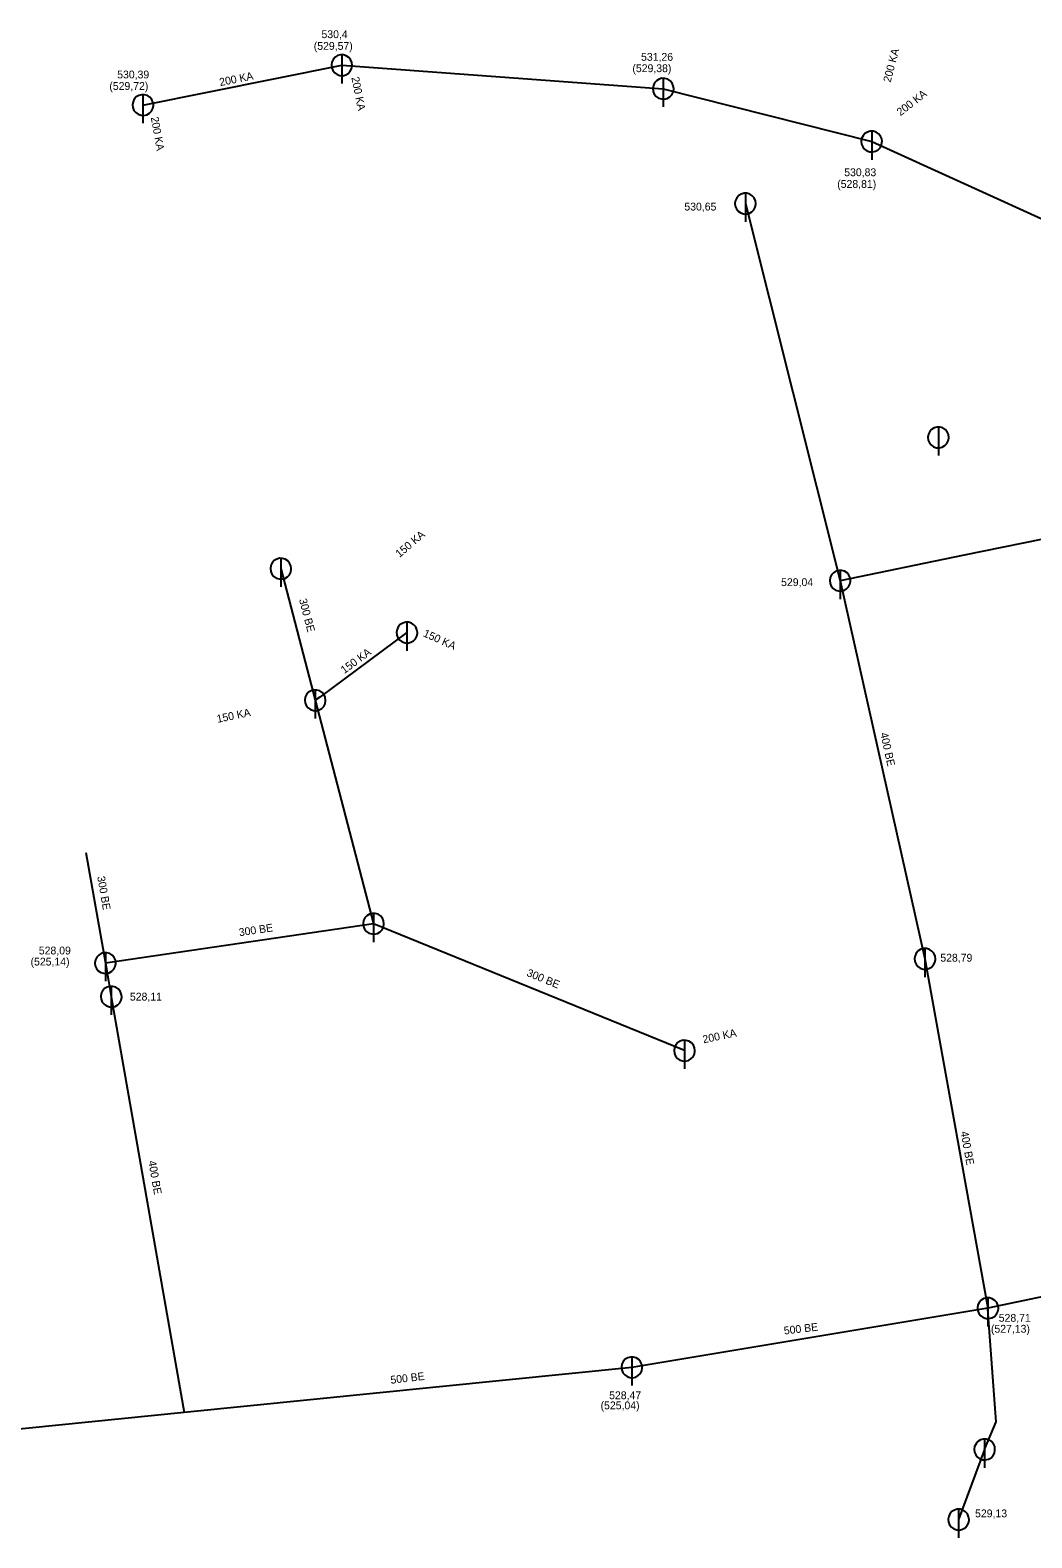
# Model space of a CAD drawing. Extents: x -476058 to -471893, y -1155786 to -1152000.
# Drawn here: x -473502.4 to -473406.3, y -1153921.9 to -1153777.4 of the extents above; entities that cross this region are included whole.
import ezdxf

# ---------------------------------------------------------------- set-up
doc = ezdxf.new("R2010")
doc.units = 0
for name, color, linetype in [('Vrstva 10', 7, 'Continuous'), ('Vrstva 18', 7, 'Continuous'), ('Vrstva 19', 7, 'Continuous'), ('Vrstva 3', 7, 'Continuous'), ('Vrstva 35', 7, 'Continuous'), ('Vrstva 4', 7, 'Continuous'), ('Vrstva 45', 7, 'Continuous'), ('Vrstva 46', 7, 'Continuous'), ('Vrstva 50', 7, 'Continuous'), ('Vrstva 51', 7, 'Continuous')]:
    doc.layers.add(name, color=color, linetype=linetype)

msp = doc.modelspace()

# ---------------------------------------------------------------- linework, layer by layer
at = {"layer": 'Vrstva 10'}
for p, q in [((-473472.48, -1153779.81), (-473472.48, -1153782.56)), ((-473441.67, -1153782.06), (-473441.67, -1153784.8)), ((-473491.54, -1153783.62), (-473491.54, -1153786.37)), ((-473421.7, -1153787.12), (-473421.7, -1153789.87)), ((-473433.8, -1153793.07), (-473433.8, -1153795.82)), ((-473415.31, -1153815.47), (-473415.31, -1153818.22)), ((-473478.32, -1153828.05), (-473478.32, -1153830.8)), ((-473424.72, -1153829.21), (-473424.72, -1153831.96)), ((-473466.24, -1153834.18), (-473466.24, -1153836.93)), ((-473475.03, -1153840.66), (-473475.03, -1153843.41)), ((-473469.44, -1153862.08), (-473469.44, -1153864.83)), ((-473495.14, -1153865.85), (-473495.14, -1153868.59)), ((-473416.59, -1153865.45), (-473416.59, -1153868.2)), ((-473494.58, -1153869.07), (-473494.58, -1153871.82)), ((-473439.64, -1153874.24), (-473439.64, -1153876.99)), ((-473410.56, -1153898.92), (-473410.56, -1153901.67)), ((-473444.68, -1153904.59), (-473444.68, -1153907.34)), ((-473410.88, -1153912.47), (-473410.88, -1153915.21)), ((-473413.37, -1153919.18), (-473413.37, -1153921.93))]:
    msp.add_line(p, q, dxfattribs=at)
for points in [[(-473471.48, -1153780.81), (-473471.52, -1153780.53), (-473471.64, -1153780.27), (-473471.82, -1153780.06), (-473472.05, -1153779.91), (-473472.33, -1153779.82), (-473472.61, -1153779.82), (-473472.88, -1153779.89), (-473473.12, -1153780.04), (-473473.31, -1153780.25), (-473473.43, -1153780.5), (-473473.48, -1153780.78), (-473473.45, -1153781.06), (-473473.34, -1153781.32), (-473473.16, -1153781.54), (-473472.93, -1153781.7), (-473472.66, -1153781.79), (-473472.38, -1153781.81), (-473472.11, -1153781.74), (-473471.86, -1153781.6), (-473471.67, -1153781.39), (-473471.54, -1153781.14), (-473471.48, -1153780.87), (-473471.48, -1153780.81)], [(-473440.67, -1153783.06), (-473440.71, -1153782.78), (-473440.83, -1153782.52), (-473441.01, -1153782.31), (-473441.25, -1153782.15), (-473441.52, -1153782.07), (-473441.8, -1153782.06), (-473442.07, -1153782.14), (-473442.31, -1153782.29), (-473442.5, -1153782.5), (-473442.62, -1153782.75), (-473442.67, -1153783.03), (-473442.64, -1153783.31), (-473442.53, -1153783.57), (-473442.35, -1153783.79), (-473442.12, -1153783.95), (-473441.85, -1153784.04), (-473441.57, -1153784.05), (-473441.3, -1153783.99), (-473441.05, -1153783.84), (-473440.86, -1153783.64), (-473440.73, -1153783.39), (-473440.67, -1153783.11), (-473440.67, -1153783.06)], [(-473490.54, -1153784.62), (-473490.58, -1153784.34), (-473490.7, -1153784.08), (-473490.88, -1153783.87), (-473491.11, -1153783.72), (-473491.39, -1153783.63), (-473491.67, -1153783.63), (-473491.94, -1153783.7), (-473492.18, -1153783.85), (-473492.37, -1153784.06), (-473492.49, -1153784.31), (-473492.54, -1153784.59), (-473492.51, -1153784.87), (-473492.4, -1153785.13), (-473492.22, -1153785.35), (-473491.99, -1153785.51), (-473491.72, -1153785.6), (-473491.44, -1153785.62), (-473491.17, -1153785.55), (-473490.92, -1153785.41), (-473490.73, -1153785.2), (-473490.6, -1153784.95), (-473490.54, -1153784.68), (-473490.54, -1153784.62)], [(-473420.7, -1153788.12), (-473420.74, -1153787.85), (-473420.86, -1153787.59), (-473421.04, -1153787.37), (-473421.28, -1153787.22), (-473421.55, -1153787.14), (-473421.83, -1153787.13), (-473422.1, -1153787.21), (-473422.34, -1153787.36), (-473422.53, -1153787.56), (-473422.66, -1153787.82), (-473422.7, -1153788.1), (-473422.67, -1153788.38), (-473422.56, -1153788.64), (-473422.39, -1153788.86), (-473422.15, -1153789.02), (-473421.89, -1153789.11), (-473421.6, -1153789.12), (-473421.33, -1153789.05), (-473421.09, -1153788.91), (-473420.89, -1153788.71), (-473420.76, -1153788.46), (-473420.71, -1153788.18), (-473420.7, -1153788.12)], [(-473432.8, -1153794.07), (-473432.84, -1153793.79), (-473432.96, -1153793.53), (-473433.14, -1153793.32), (-473433.38, -1153793.17), (-473433.65, -1153793.08), (-473433.93, -1153793.08), (-473434.2, -1153793.15), (-473434.44, -1153793.3), (-473434.63, -1153793.51), (-473434.75, -1153793.76), (-473434.8, -1153794.04), (-473434.77, -1153794.32), (-473434.66, -1153794.58), (-473434.48, -1153794.8), (-473434.25, -1153794.96), (-473433.98, -1153795.05), (-473433.7, -1153795.07), (-473433.43, -1153795), (-473433.18, -1153794.86), (-473432.99, -1153794.65), (-473432.86, -1153794.4), (-473432.8, -1153794.13), (-473432.8, -1153794.07)], [(-473414.31, -1153816.47), (-473414.35, -1153816.19), (-473414.47, -1153815.94), (-473414.65, -1153815.72), (-473414.88, -1153815.57), (-473415.15, -1153815.48), (-473415.44, -1153815.48), (-473415.71, -1153815.55), (-473415.95, -1153815.7), (-473416.14, -1153815.91), (-473416.26, -1153816.17), (-473416.31, -1153816.44), (-473416.28, -1153816.73), (-473416.17, -1153816.99), (-473415.99, -1153817.2), (-473415.76, -1153817.37), (-473415.49, -1153817.46), (-473415.21, -1153817.47), (-473414.93, -1153817.4), (-473414.69, -1153817.26), (-473414.5, -1153817.05), (-473414.37, -1153816.8), (-473414.31, -1153816.53), (-473414.31, -1153816.47)], [(-473477.32, -1153829.05), (-473477.36, -1153828.78), (-473477.48, -1153828.52), (-473477.66, -1153828.3), (-473477.9, -1153828.15), (-473478.17, -1153828.07), (-473478.45, -1153828.06), (-473478.72, -1153828.14), (-473478.96, -1153828.28), (-473479.15, -1153828.49), (-473479.27, -1153828.75), (-473479.32, -1153829.03), (-473479.29, -1153829.31), (-473479.18, -1153829.57), (-473479, -1153829.79), (-473478.77, -1153829.95), (-473478.5, -1153830.04), (-473478.22, -1153830.05), (-473477.95, -1153829.98), (-473477.7, -1153829.84), (-473477.51, -1153829.64), (-473477.38, -1153829.39), (-473477.32, -1153829.11), (-473477.32, -1153829.05)], [(-473423.72, -1153830.21), (-473423.76, -1153829.93), (-473423.88, -1153829.67), (-473424.06, -1153829.46), (-473424.29, -1153829.3), (-473424.57, -1153829.22), (-473424.85, -1153829.22), (-473425.12, -1153829.29), (-473425.36, -1153829.44), (-473425.55, -1153829.65), (-473425.67, -1153829.9), (-473425.72, -1153830.18), (-473425.69, -1153830.46), (-473425.58, -1153830.72), (-473425.4, -1153830.94), (-473425.17, -1153831.1), (-473424.9, -1153831.19), (-473424.62, -1153831.21), (-473424.35, -1153831.14), (-473424.1, -1153831), (-473423.91, -1153830.79), (-473423.78, -1153830.54), (-473423.72, -1153830.27), (-473423.72, -1153830.21)], [(-473465.24, -1153835.18), (-473465.28, -1153834.9), (-473465.39, -1153834.64), (-473465.58, -1153834.43), (-473465.81, -1153834.28), (-473466.08, -1153834.19), (-473466.36, -1153834.19), (-473466.64, -1153834.26), (-473466.88, -1153834.41), (-473467.07, -1153834.62), (-473467.19, -1153834.87), (-473467.24, -1153835.15), (-473467.2, -1153835.43), (-473467.1, -1153835.69), (-473466.92, -1153835.91), (-473466.69, -1153836.07), (-473466.42, -1153836.16), (-473466.14, -1153836.18), (-473465.86, -1153836.11), (-473465.62, -1153835.97), (-473465.42, -1153835.76), (-473465.29, -1153835.51), (-473465.24, -1153835.24), (-473465.24, -1153835.18)], [(-473474.03, -1153841.66), (-473474.07, -1153841.38), (-473474.18, -1153841.13), (-473474.37, -1153840.91), (-473474.6, -1153840.76), (-473474.87, -1153840.68), (-473475.16, -1153840.67), (-473475.43, -1153840.75), (-473475.67, -1153840.89), (-473475.86, -1153841.1), (-473475.98, -1153841.36), (-473476.03, -1153841.64), (-473476, -1153841.92), (-473475.89, -1153842.18), (-473475.71, -1153842.4), (-473475.48, -1153842.56), (-473475.21, -1153842.65), (-473474.93, -1153842.66), (-473474.66, -1153842.59), (-473474.41, -1153842.45), (-473474.22, -1153842.25), (-473474.09, -1153842), (-473474.03, -1153841.72), (-473474.03, -1153841.66)], [(-473468.44, -1153863.08), (-473468.48, -1153862.8), (-473468.59, -1153862.54), (-473468.78, -1153862.33), (-473469.01, -1153862.17), (-473469.28, -1153862.09), (-473469.56, -1153862.09), (-473469.84, -1153862.16), (-473470.08, -1153862.31), (-473470.27, -1153862.52), (-473470.39, -1153862.77), (-473470.44, -1153863.05), (-473470.41, -1153863.33), (-473470.3, -1153863.59), (-473470.12, -1153863.81), (-473469.89, -1153863.97), (-473469.62, -1153864.06), (-473469.34, -1153864.07), (-473469.06, -1153864.01), (-473468.82, -1153863.86), (-473468.62, -1153863.66), (-473468.49, -1153863.41), (-473468.44, -1153863.13), (-473468.44, -1153863.08)], [(-473494.14, -1153866.85), (-473494.18, -1153866.57), (-473494.3, -1153866.31), (-473494.48, -1153866.09), (-473494.72, -1153865.94), (-473494.99, -1153865.86), (-473495.27, -1153865.85), (-473495.54, -1153865.93), (-473495.78, -1153866.08), (-473495.97, -1153866.29), (-473496.1, -1153866.54), (-473496.14, -1153866.82), (-473496.11, -1153867.1), (-473496, -1153867.36), (-473495.83, -1153867.58), (-473495.59, -1153867.74), (-473495.33, -1153867.83), (-473495.04, -1153867.84), (-473494.77, -1153867.77), (-473494.53, -1153867.63), (-473494.33, -1153867.43), (-473494.2, -1153867.18), (-473494.15, -1153866.9), (-473494.14, -1153866.85)], [(-473415.59, -1153866.45), (-473415.63, -1153866.17), (-473415.75, -1153865.91), (-473415.93, -1153865.7), (-473416.17, -1153865.54), (-473416.43, -1153865.46), (-473416.72, -1153865.46), (-473416.99, -1153865.53), (-473417.23, -1153865.68), (-473417.42, -1153865.89), (-473417.54, -1153866.14), (-473417.59, -1153866.42), (-473417.56, -1153866.7), (-473417.45, -1153866.96), (-473417.27, -1153867.18), (-473417.04, -1153867.34), (-473416.77, -1153867.43), (-473416.49, -1153867.45), (-473416.22, -1153867.38), (-473415.97, -1153867.24), (-473415.78, -1153867.03), (-473415.65, -1153866.78), (-473415.59, -1153866.51), (-473415.59, -1153866.45)], [(-473493.58, -1153870.07), (-473493.62, -1153869.79), (-473493.73, -1153869.53), (-473493.92, -1153869.32), (-473494.15, -1153869.16), (-473494.42, -1153869.08), (-473494.71, -1153869.08), (-473494.98, -1153869.15), (-473495.22, -1153869.3), (-473495.41, -1153869.51), (-473495.53, -1153869.76), (-473495.58, -1153870.04), (-473495.55, -1153870.32), (-473495.44, -1153870.58), (-473495.26, -1153870.8), (-473495.03, -1153870.96), (-473494.76, -1153871.05), (-473494.48, -1153871.06), (-473494.2, -1153871), (-473493.96, -1153870.85), (-473493.77, -1153870.65), (-473493.64, -1153870.4), (-473493.58, -1153870.12), (-473493.58, -1153870.07)], [(-473438.64, -1153875.24), (-473438.68, -1153874.96), (-473438.79, -1153874.71), (-473438.98, -1153874.49), (-473439.21, -1153874.34), (-473439.48, -1153874.26), (-473439.76, -1153874.25), (-473440.04, -1153874.33), (-473440.28, -1153874.47), (-473440.47, -1153874.68), (-473440.59, -1153874.94), (-473440.64, -1153875.22), (-473440.6, -1153875.5), (-473440.5, -1153875.76), (-473440.32, -1153875.98), (-473440.09, -1153876.14), (-473439.82, -1153876.23), (-473439.54, -1153876.24), (-473439.26, -1153876.17), (-473439.02, -1153876.03), (-473438.82, -1153875.83), (-473438.69, -1153875.58), (-473438.64, -1153875.3), (-473438.64, -1153875.24)], [(-473409.56, -1153899.92), (-473409.6, -1153899.64), (-473409.72, -1153899.38), (-473409.9, -1153899.17), (-473410.14, -1153899.02), (-473410.41, -1153898.93), (-473410.69, -1153898.93), (-473410.96, -1153899), (-473411.2, -1153899.15), (-473411.39, -1153899.36), (-473411.51, -1153899.61), (-473411.56, -1153899.89), (-473411.53, -1153900.17), (-473411.42, -1153900.43), (-473411.24, -1153900.65), (-473411.01, -1153900.81), (-473410.74, -1153900.9), (-473410.46, -1153900.92), (-473410.19, -1153900.85), (-473409.94, -1153900.71), (-473409.75, -1153900.5), (-473409.62, -1153900.25), (-473409.56, -1153899.98), (-473409.56, -1153899.92)], [(-473443.68, -1153905.59), (-473443.72, -1153905.31), (-473443.84, -1153905.05), (-473444.02, -1153904.84), (-473444.26, -1153904.68), (-473444.53, -1153904.6), (-473444.81, -1153904.6), (-473445.08, -1153904.67), (-473445.32, -1153904.82), (-473445.51, -1153905.03), (-473445.64, -1153905.28), (-473445.68, -1153905.56), (-473445.65, -1153905.84), (-473445.54, -1153906.1), (-473445.37, -1153906.32), (-473445.14, -1153906.48), (-473444.87, -1153906.57), (-473444.59, -1153906.58), (-473444.31, -1153906.52), (-473444.07, -1153906.38), (-473443.87, -1153906.17), (-473443.74, -1153905.92), (-473443.69, -1153905.64), (-473443.68, -1153905.59)], [(-473409.88, -1153913.47), (-473409.91, -1153913.19), (-473410.03, -1153912.93), (-473410.21, -1153912.71), (-473410.45, -1153912.56), (-473410.72, -1153912.48), (-473411, -1153912.47), (-473411.27, -1153912.55), (-473411.51, -1153912.7), (-473411.7, -1153912.91), (-473411.83, -1153913.16), (-473411.88, -1153913.44), (-473411.84, -1153913.72), (-473411.73, -1153913.98), (-473411.56, -1153914.2), (-473411.33, -1153914.36), (-473411.06, -1153914.45), (-473410.78, -1153914.46), (-473410.5, -1153914.39), (-473410.26, -1153914.25), (-473410.06, -1153914.05), (-473409.93, -1153913.8), (-473409.88, -1153913.52), (-473409.88, -1153913.47)], [(-473412.37, -1153920.18), (-473412.41, -1153919.9), (-473412.53, -1153919.64), (-473412.71, -1153919.43), (-473412.94, -1153919.28), (-473413.21, -1153919.19), (-473413.5, -1153919.19), (-473413.77, -1153919.26), (-473414.01, -1153919.41), (-473414.2, -1153919.62), (-473414.32, -1153919.87), (-473414.37, -1153920.15), (-473414.34, -1153920.43), (-473414.23, -1153920.69), (-473414.05, -1153920.91), (-473413.82, -1153921.07), (-473413.55, -1153921.16), (-473413.27, -1153921.18), (-473412.99, -1153921.11), (-473412.75, -1153920.97), (-473412.56, -1153920.76), (-473412.43, -1153920.51), (-473412.37, -1153920.24), (-473412.37, -1153920.18)]]:
    msp.add_lwpolyline(points, dxfattribs=at)
at = {"layer": 'Vrstva 35'}
msp.add_lwpolyline([(-473433.8, -1153794.07), (-473424.72, -1153830.21)], dxfattribs=at)
at = {"layer": 'Vrstva 45'}
for points in [[(-473491.54, -1153784.62), (-473472.48, -1153780.81)], [(-473472.48, -1153780.81), (-473441.67, -1153783.06)], [(-473441.67, -1153783.06), (-473421.7, -1153788.12)], [(-473421.7, -1153788.12), (-473404, -1153796.17)], [(-473403.26, -1153825.81), (-473412.99, -1153827.8)], [(-473412.99, -1153827.8), (-473424.72, -1153830.21)], [(-473424.72, -1153830.21), (-473416.59, -1153866.45)], [(-473416.59, -1153866.45), (-473410.56, -1153899.92)], [(-473495.14, -1153866.85), (-473494.85, -1153868.54)], [(-473494.85, -1153868.54), (-473494.58, -1153870.07)], [(-473401.72, -1153898.07), (-473410.56, -1153899.92)], [(-473410.56, -1153899.92), (-473444.68, -1153905.59)]]:
    msp.add_lwpolyline(points, dxfattribs=at)
at = {"layer": 'Vrstva 46'}
for points in [[(-473478.32, -1153829.05), (-473475.03, -1153841.66)], [(-473475.03, -1153841.66), (-473469.44, -1153863.08)], [(-473497, -1153856.26), (-473495.14, -1153866.85)], [(-473469.44, -1153863.08), (-473495.14, -1153866.85)], [(-473439.64, -1153875.24), (-473469.44, -1153863.08)], [(-473494.58, -1153870.07), (-473487.58, -1153909.91)], [(-473444.68, -1153905.59), (-473487.58, -1153909.91)], [(-473487.58, -1153909.91), (-473544.84, -1153915.69)]]:
    msp.add_lwpolyline(points, dxfattribs=at)
at = {"layer": 'Vrstva 50'}
for points in [[(-473410.88, -1153913.47), (-473409.77, -1153910.81), (-473410.52, -1153900.45)], [(-473410.52, -1153900.45), (-473410.56, -1153899.92)], [(-473410.88, -1153913.47), (-473413.37, -1153920.18)]]:
    msp.add_lwpolyline(points, dxfattribs=at)
at = {"layer": 'Vrstva 51'}
msp.add_lwpolyline([(-473466.24, -1153835.18), (-473474.6, -1153841.35), (-473475.03, -1153841.66)], dxfattribs=at)

# ---------------------------------------------------------------- texts
at = {"layer": 'Vrstva 18'}
for s, rotation, p in [('200 KA', 11.3042, (-473484.14, -1153782.81)), ('300 BE', 284.6366, (-473476.59, -1153832.01)), ('400 BE', 282.6443, (-473420.89, -1153844.84)), ('300 BE', 279.9366, (-473495.93, -1153858.58)), ('300 BE', 8.3387, (-473482.29, -1153864.28)), ('300 BE', 337.7937, (-473454.83, -1153868.06)), ('400 BE', 280.2129, (-473413.18, -1153883.03)), ('400 BE', 279.963, (-473491.03, -1153885.84)), ('500 BE', 6.6983, (-473430.07, -1153902.45)), ('500 BE', 6.6976, (-473467.78, -1153907.17))]:
    msp.add_text(s, height=0.75, rotation=rotation, dxfattribs=at).set_placement(p)
at = {"layer": 'Vrstva 19'}
for s, rotation, p in [('200 KA', 75.2679, (-473419.89, -1153782.5)), ('200 KA', 281.2621, (-473471.57, -1153781.99)), ('200 KA', 37.7471, (-473418.94, -1153785.7)), ('200 KA', 280.0276, (-473490.79, -1153785.81)), ('150 KA', 40.3237, (-473466.95, -1153828.03)), ('150 KA', 335.7467, (-473464.75, -1153835.51)), ('150 KA', 36.4012, (-473472.24, -1153839.16)), ('150 KA', 11.7356, (-473484.39, -1153843.83)), ('200 KA', 11.6681, (-473437.82, -1153874.54))]:
    msp.add_text(s, height=0.75, rotation=rotation, dxfattribs=at).set_placement(p)
at = {"layer": 'Vrstva 3'}
for s, p in [('530,4', (-473474.43, -1153778.21)), ('531,26', (-473443.8, -1153780.38)), ('530,39', (-473494.01, -1153782.07)), ('530,83', (-473424.33, -1153791.44)), ('530,65', (-473439.65, -1153794.73)), ('529,04', (-473430.38, -1153830.72)), ('528,09', (-473501.52, -1153866.02)), ('528,79', (-473415.12, -1153866.71)), ('528,11', (-473492.79, -1153870.44)), ('528,71', (-473409.52, -1153901.22)), ('528,47', (-473446.86, -1153908.64)), ('529,13', (-473411.79, -1153919.96))]:
    msp.add_text(s, height=0.75, dxfattribs=at).set_placement(p)
at = {"layer": 'Vrstva 4'}
for s, p in [('(529,57)', (-473475.17, -1153779.33)), ('(529,38)', (-473444.63, -1153781.47)), ('(529,72)', (-473494.76, -1153783.17)), ('(528,81)', (-473425, -1153792.56)), ('(525,14)', (-473502.31, -1153867.08)), ('(527,13)', (-473410.27, -1153902.27)), ('(525,04)', (-473447.68, -1153909.61))]:
    msp.add_text(s, height=0.75, dxfattribs=at).set_placement(p)

doc.saveas('drawing.dxf')
